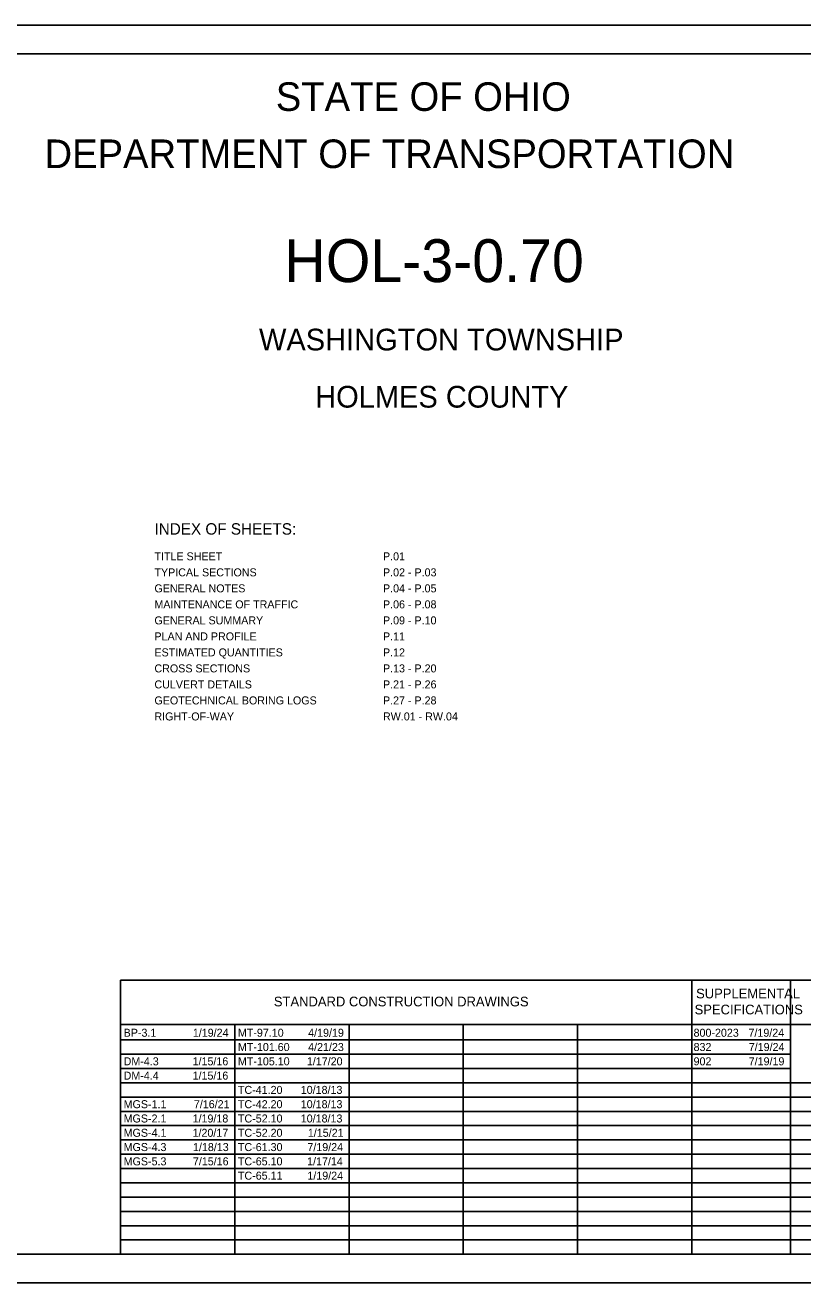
# Model space of a CAD drawing. Extents: x -7.5 to 53.5, y 0 to 22.
# Drawn here: x 9.58 to 23.19, y 0 to 22 of the extents above; entities that cross this region are included whole.
import ezdxf

# ---------------------------------------------------------------- set-up
doc = ezdxf.new("R2010")
doc.units = 0
for name, color, linetype in [('SH_Border', 7, 'Continuous'), ('SH_Cut_Line', 7, 'Continuous'), ('SH_Data', 7, 'Continuous'), ('SH_Text', 7, 'Continuous')]:
    doc.layers.add(name, color=color, linetype=linetype)

msp = doc.modelspace()

# ---------------------------------------------------------------- linework, layer by layer
at = {"layer": 'SH_Border'}
msp.add_lwpolyline([(1.5, 21.5), (33.5, 21.5), (33.5, 0.5), (1.5, 0.5)], close=True, dxfattribs=at)
at = {"layer": 'SH_Cut_Line'}
msp.add_lwpolyline([(0, 0), (34, 0), (34, 22), (0, 22)], close=True, dxfattribs=at)
at = {"layer": 'SH_Data'}
for p, q in [((11.25, 5.292), (24.7, 5.292)), ((11.25, 0.5), (11.25, 5.292)), ((21.25, 0.5), (21.25, 5.292)), ((22.975, 0.5), (22.975, 5.292)), ((11.25, 4.521), (24.7, 4.521)), ((13.25, 0.5), (13.25, 4.521)), ((15.25, 0.5), (15.25, 4.521)), ((17.25, 0.5), (17.25, 4.521)), ((19.25, 0.5), (19.25, 4.521)), ((11.25, 4.25), (22.975, 4.25)), ((11.25, 4), (22.975, 4)), ((11.25, 3.75), (22.975, 3.75)), ((11.25, 3.5), (24.7, 3.5)), ((11.25, 3.25), (24.7, 3.25)), ((11.25, 3), (24.7, 3)), ((11.25, 2.75), (24.7, 2.75)), ((11.25, 2.5), (24.7, 2.5)), ((11.25, 2.25), (24.7, 2.25)), ((11.25, 2), (24.7, 2)), ((11.25, 1.75), (24.7, 1.75)), ((11.25, 1.5), (24.7, 1.5)), ((11.25, 1.25), (24.7, 1.25)), ((11.25, 1), (24.7, 1)), ((11.25, 0.75), (24.7, 0.75))]:
    msp.add_line(p, q, dxfattribs=at)

# ---------------------------------------------------------------- texts
for s, p in [('BP-3.1', (11.305, 4.305)), ('1/19/24', (12.516, 4.305)), ('MT-97.10', (13.305, 4.305)), ('4/19/19', (14.535, 4.305)), ('800-2023', (21.28, 4.305)), ('7/19/24', (22.241, 4.305)), ('MT-101.60', (13.305, 4.055)), ('4/21/23', (14.534, 4.055)), ('832', (21.28, 4.055)), ('7/19/24', (22.246, 4.055)), ('DM-4.3', (11.305, 3.805)), ('1/15/16', (12.512, 3.805)), ('MT-105.10', (13.305, 3.805)), ('1/17/20', (14.512, 3.805)), ('902', (21.28, 3.805)), ('7/19/19', (22.245, 3.805)), ('DM-4.4', (11.305, 3.555)), ('1/15/16', (12.512, 3.555)), ('TC-41.20', (13.305, 3.305)), ('10/18/13', (14.405, 3.305)), ('MGS-1.1', (11.305, 3.055)), ('7/16/21', (12.534, 3.055)), ('TC-42.20', (13.305, 3.055)), ('10/18/13', (14.405, 3.055)), ('MGS-2.1', (11.305, 2.805)), ('1/19/18', (12.512, 2.805)), ('TC-52.10', (13.305, 2.805)), ('10/18/13', (14.405, 2.805)), ('MGS-4.1', (11.305, 2.555)), ('1/20/17', (12.511, 2.555)), ('TC-52.20', (13.305, 2.555)), ('1/15/21', (14.529, 2.555)), ('MGS-4.3', (11.305, 2.305)), ('1/18/13', (12.519, 2.305)), ('TC-61.30', (13.305, 2.305)), ('7/19/24', (14.521, 2.305)), ('7/15/16', (12.517, 2.055)), ('1/17/14', (14.516, 2.055)), ('MGS-5.3', (11.305, 2.055)), ('TC-65.10', (13.305, 2.055)), ('TC-65.11', (13.305, 1.805)), ('1/19/24', (14.521, 1.805))]:
    msp.add_text(s, height=0.14, dxfattribs=at).set_placement(p)
at = {"layer": 'SH_Text'}
for s, height, p in [('STATE OF OHIO', 0.5, (13.968, 20.5)), ('DEPARTMENT OF TRANSPORTATION', 0.5, (9.92, 19.5)), ('HOL-3-0.70', 0.75, (14.119, 17.505)), ('WASHINGTON TOWNSHIP', 0.38, (13.674, 16.31)), ('HOLMES COUNTY', 0.38, (14.657, 15.31)), ('INDEX OF SHEETS:', 0.2, (11.844, 13.088)), ('TITLE SHEET', 0.14, (11.844, 12.638)), ('P.01', 0.14, (15.844, 12.638)), ('TYPICAL SECTIONS', 0.14, (11.844, 12.358)), ('P.02 - P.03', 0.14, (15.844, 12.358)), ('GENERAL NOTES', 0.14, (11.844, 12.078)), ('P.04 - P.05', 0.14, (15.844, 12.078)), ('MAINTENANCE OF TRAFFIC', 0.14, (11.844, 11.798)), ('P.06 - P.08', 0.14, (15.844, 11.798)), ('GENERAL SUMMARY', 0.14, (11.844, 11.518)), ('P.09 - P.10', 0.14, (15.844, 11.518)), ('PLAN AND PROFILE', 0.14, (11.844, 11.238)), ('P.11', 0.14, (15.844, 11.238)), ('ESTIMATED QUANTITIES', 0.14, (11.844, 10.958)), ('P.12', 0.14, (15.844, 10.958)), ('CROSS SECTIONS', 0.14, (11.844, 10.678)), ('P.13 - P.20', 0.14, (15.844, 10.678)), ('CULVERT DETAILS', 0.14, (11.844, 10.398)), ('P.21 - P.26', 0.14, (15.844, 10.398)), ('GEOTECHNICAL BORING LOGS', 0.14, (11.844, 10.118)), ('P.27 - P.28', 0.14, (15.844, 10.118)), ('RIGHT-OF-WAY', 0.14, (11.844, 9.838)), ('RW.01 - RW.04', 0.14, (15.844, 9.838)), ('SUPPLEMENTAL', 0.17, (21.324, 4.976)), ('STANDARD CONSTRUCTION DRAWINGS', 0.17, (13.934, 4.836)), ('SPECIFICATIONS', 0.17, (21.298, 4.696))]:
    msp.add_text(s, height=height, dxfattribs=at).set_placement(p)

doc.saveas('drawing.dxf')
